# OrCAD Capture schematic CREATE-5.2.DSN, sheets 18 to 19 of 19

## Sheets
18 P16: Back access 50 pin conn: size Custom; title: Bottom Conn
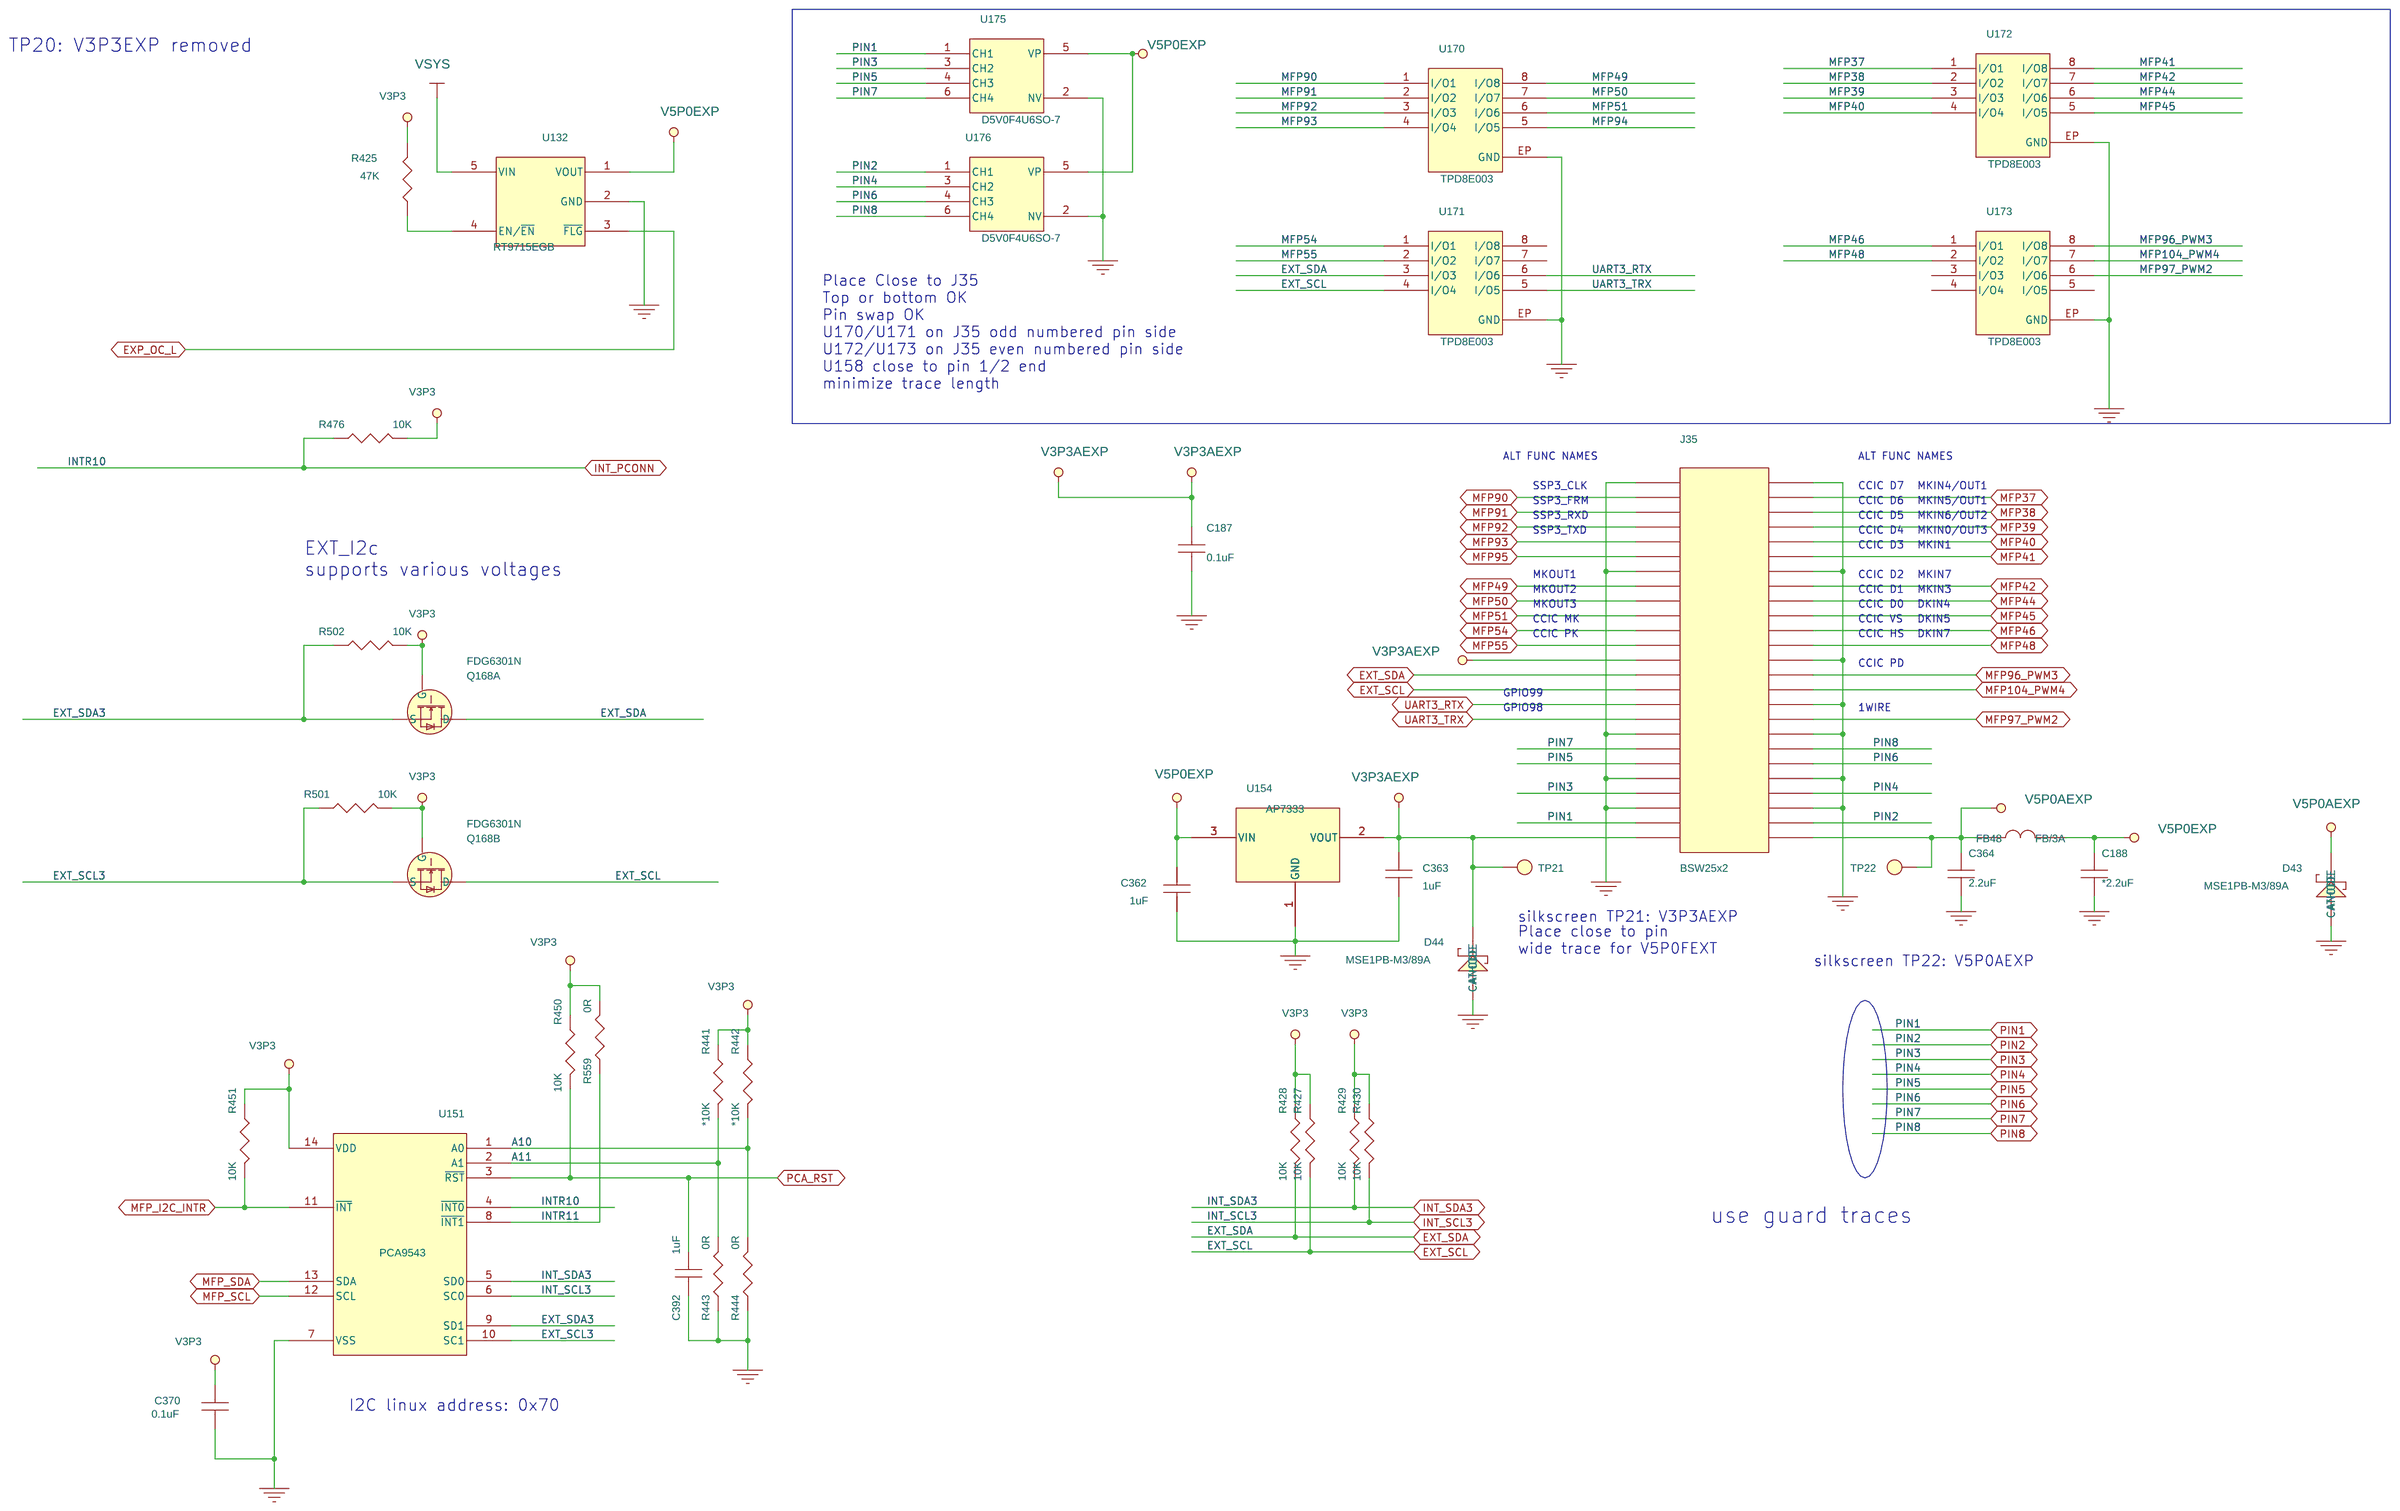
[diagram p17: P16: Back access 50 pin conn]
19 P15: Front access 8 pin conn 2: size Custom; title: Front Conn 2
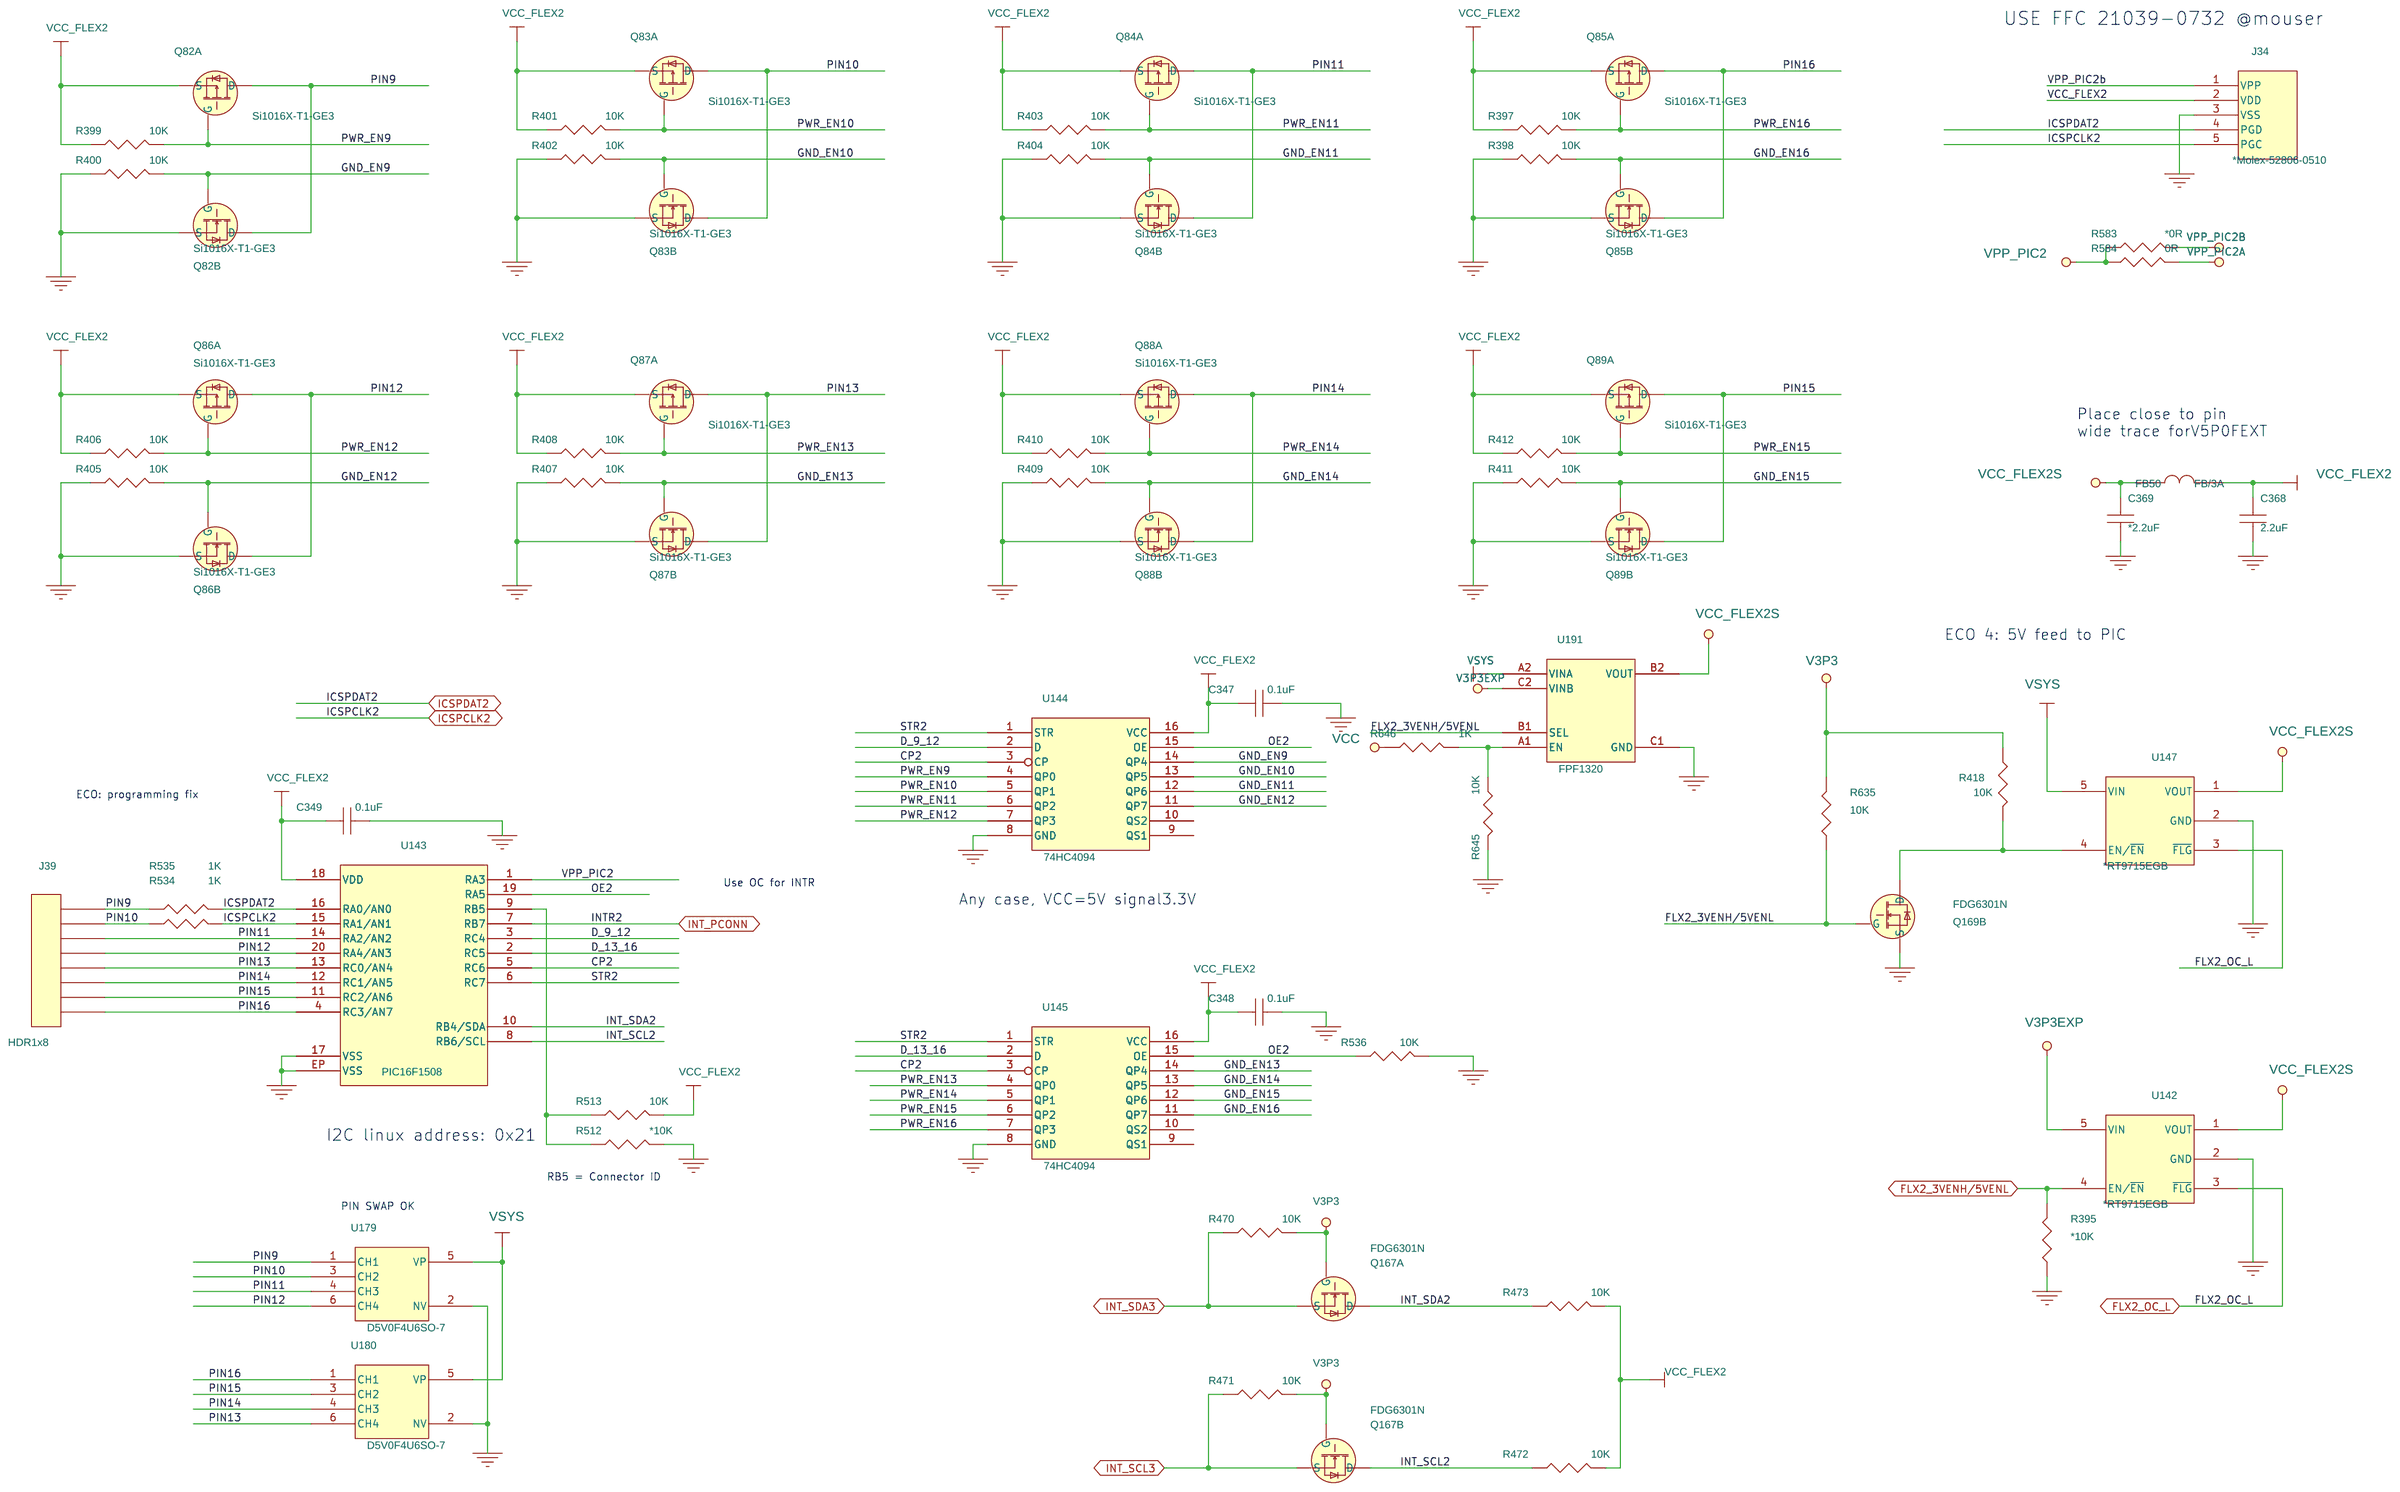
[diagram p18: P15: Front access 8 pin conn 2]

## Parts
sheet P14: Front access 8 pin conn 1
Q169  FDG6301N  [SC70-6]  (sections A,B)
sheet P15: Front access 8 pin conn 2
C347  0.1uF  [C-0402]
C348  0.1uF  [C-0402]
C349  0.1uF  [C-0402]
C368  2.2uF  [C-0402]
C369  *2.2uF  [C-0402]
FB50  FB/3A  [L-0603]
J34  *Molex-52806-0510  [Molex_52806_0510]
J39  HDR1x8  [HDR1x8_100milSMT]
Q82  Si1016X-T1-GE3  [SOT563]  (sections A,B)
Q83  Si1016X-T1-GE3  [SOT563]  (sections A,B)
Q84  Si1016X-T1-GE3  [SOT563]  (sections A,B)
Q85  Si1016X-T1-GE3  [SOT563]  (sections A,B)
Q86  Si1016X-T1-GE3  [SOT563]  (sections A,B)
Q87  Si1016X-T1-GE3  [SOT563]  (sections A,B)
Q88  Si1016X-T1-GE3  [SOT563]  (sections A,B)
Q89  Si1016X-T1-GE3  [SOT563]  (sections A,B)
Q167  FDG6301N  [SC70-6]  (sections A,B)
R395  *10K  [R-0402]
R397  10K  [R-0201]
R398  10K  [R-0201]
R399  10K  [R-0201]
R400  10K  [R-0201]
R401  10K  [R-0201]
R402  10K  [R-0201]
R403  10K  [R-0201]
R404  10K  [R-0201]
R405  10K  [R-0201]
R406  10K  [R-0201]
R407  10K  [R-0201]
R408  10K  [R-0201]
R409  10K  [R-0201]
R410  10K  [R-0201]
R411  10K  [R-0201]
R412  10K  [R-0201]
R418  10K  [R-0201]
R470  10K  [R-0201]
R471  10K  [R-0201]
R472  10K  [R-0201]
R473  10K  [R-0201]
R512  *10K  [R-0201]
R513  10K  [R-0201]
R534  1K  [R-0402]
R535  1K  [R-0402]
R536  10K  [R-0201]
R583  *0R  [R-0402]
R584  0R  [R-0402]
R635  10K  [R-0201]
R645  10K  [R-0402]
R646  1K  [R-0402]
U142  *RT9715EGB  [SOT23-5]
U143  PIC16F1508  [QFN20]
U144  74HC4094  [TSSOP16]
U145  74HC4094  [TSSOP16]
U147  *RT9715EGB  [SOT23-5]
U179  D5V0F4U6SO-7  [SC-74]
U180  D5V0F4U6SO-7  [SC-74]
U191  FPF1320  [6WLCSP]
sheet P16: Back access 50 pin conn
C187  0.1uF  [C-0402]
C188  *2.2uF  [C-0402]
C362  1uF  [C0402]
C363  1uF  [C0402]
C364  2.2uF  [C-0402]
C370  0.1uF  [C-0402]
C392  1uF  [C0402]
D43  MSE1PB-M3/89A  [MicroSMP]
D44  MSE1PB-M3/89A  [MicroSMP]
FB48  FB/3A  [L-0603]
J35  BSW25x2  [RCPT25x2_100mil_BOT]
Q168  FDG6301N  [SC70-6]  (sections A,B)
R425  47K  [R-0402]
R427  10K  [R-0402]
R428  10K  [R-0402]
R429  10K  [R-0402]
R430  10K  [R-0402]
R441  *10K  [R-0402]
R442  *10K  [R-0402]
R443  0R  [R-0402]
R444  0R  [R-0402]
R450  10K  [R-0402]
R451  10K  [R-0402]
R476  10K  [R-0402]
R501  10K  [R-0402]
R502  10K  [R-0402]
R559  0R  [R-0402]
TP21  *T_POINT  [TP040]
TP22  *T_POINT  [TP040]
U132  RT9715EGB  [SOT23-5]
U151  PCA9543  [soic14-50-157]
U154  AP7333  [SOT23R]
U170  TPD8E003  [WSON8EP]
U171  TPD8E003  [WSON8EP]
U172  TPD8E003  [WSON8EP]
U173  TPD8E003  [WSON8EP]
U175  D5V0F4U6SO-7  [SC-74]
U176  D5V0F4U6SO-7  [SC-74]

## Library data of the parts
Q169 = NMOS-DUAL6-sc70: Desc: MOSFET 2N-CH 25V 0.22A SC70-6; Vendor: Fairchild; x: MOSFET 2N-CH 25V 0.22A SC70-6
C347-C349 = CAPACITOR_NON-POL: Desc: CAP CER .10UF 10V X7R 0402; OPTION: DBG; Part Num: C1005X7R1A104K; Vendor: TDK
C188 C364 C368 C369 = CAP_NP_2: Desc: CAP CER 2.2UF 10V 10% X5R 0402; Part Num: C1005X5R1A225K; Vendor: TDK
FB48 FB50 = FERRITE_BEAD_0: Desc: FERRITE CHIP 120 OHM 3000MA 0603; Part Num: BLM18KG121TN1; Vendor: Murata
J34 = PIC_DEBUG_PAD: Desc: CONN FFC/FPC 5POS 1MM VERT T/H; Part Num: 52806-0510; Vendor: Molex
J39 = CON8: Desc: CONN HEADER FEMALE 8POS .1" GOLD; Part Num: SSM-108-F-SV; Vendor: Samtec
Q82-Q89 = CMOS-DUAL: Desc: MOSFET N/P-CH 20V 600/350 SC89-6; Vendor: Vishay
Q167 Q168 = NMOS-DUAL6-sc70: Desc: MOSFET 2N-CH 25V 0.22A SC70-6; Vendor: Fairchild
R395 R418 = R_0: Desc: RES 10K OHM 1/20W 5% 0201 SMD; Mfr: Generic; Part Num: ERJ-1GEJ103C; Vendor: Panasonic; d: RES 1K OHM 1/10W 1% 0402 SMD
R397-R412 R645 = R_0: Desc: RES 10K OHM 1/20W 5% 0201 SMD; Mfr: Generic; Part Num: ERJ-1GEJ103C; Vendor: Panasonic
R470 R471 R512 R513 R536 R635 = Res_0: Desc: RES 10K OHM 1/20W 5% 0201 SMD; Part Num: ERJ-1GEJ103C; Vendor: Panasonic
R472 R473 = Res_0: Desc: RES 10K OHM 1/20W 5% 0201 SMD; Mfr: Generic; Part Num: ERJ-1GEJ103C; Vendor: Panasonic
R534 R535 = Res_0: Desc: RES 1K OHM 1/10W 1% 0402 SMD; Mfr: Generic; Part Num: ERJ-2RKF1001X; Vendor: Panasonic
R583 = Res_0: Desc: RES 0.0 OHM 1/10W 0402 SMD; Mfr: Generic; Part Num: ERJ-2GE0R00X; Vendor: Panasonic
R584 = Res_0: Desc: RES 0.0 OHM 1/10W 0402 SMD; Mfr: Generic; Part Num: ERJ-2GE0R00X; Vendor: Panasonic; ccc: RES 0.0 OHM 1/10W 0402 SMD
R646 = Res_0: Desc: RES 1K OHM 1/10W 1% 0402 SMD; Part Num: ERJ-2RKF1001X; Vendor: Panasonic
U142 U147 = RT9517SOT23-5: Desc: IC PWR SW USB 1.1A SOT23-5; Part Num: RT9715EGB; Vendor: Richtek
U143 = PIC16F1508QFN: Vendor: microchip
U144 U145 = 74HC4094
U175 U176 U179 U180 = CM1293A: Desc: TVS DIODE 5.5VWM 12VC SOT26; Vendor: Diodes
U191 = FPF1321
C187 = CAP_NP: Desc: CAP CER .10UF 10V X7R 0402; Function Code: VGA; Part Num: C1005X7R1A104K; Part Number: CH41006K911; Vendor: TDK
C362 C363 C392 = CAP_NP_0: Desc: CAP CER 1UF 10V 10% X5R 0402; OPTION: LIPO; Part Num: C1005X5R1A105K050BB; Vendor: TDK; ccc: CAP CER 1UF 10V 10% X5R 0402
C370 = CAP_NP_1: Desc: CAP CER .10UF 10V X7R 0402; Part Num: C1005X7R1A104K; Vendor: TDK
D43 D44 = DIODE_SCHOTTKY: Desc: DIODE ESD PROT 1A 100V MICROSMP; Vendor: Vishay
J35 = CON50A: Desc: CONN RCPT 50POS .100" DBL GOLD BOTTOM ENTRY; Part Num: BSW-125-04-L-D; Vendor: Samtec
R425 = Res_0: Desc: RES 47K OHM 1/10W 1% 0402 SMD; Part Num: ERJ-2RKF4702X; Vendor: Panasonic
R427-R430 R441 R442 R450 R451 = Res_0: Desc: RES 10K OHM 1/10W 5% 0402 SMD; Mfr: Generic; Part Num: ERJ-2GEJ103X; Vendor: Panasonic
R443 R444 R559 = R_0: Desc: RES 0.0 OHM 1/10W 0402 SMD; Mfr: Generic; Part Num: ERJ-2GE0R00X; Vendor: Panasonic
R476 R501 R502 = Res_0: Desc: RES 10K OHM 1/10W 5% 0402 SMD; Part Num: ERJ-2GEJ103X; Vendor: Panasonic
TP21 TP22 = T_POINT: Desc: SMT Test Point; Part Num: NA; Vendor: Test
U132 = RT9517SOT23-5: Desc: IC PWR SW USB 1.1A SOT23-5; Vendor: Richtek
U151 = PCA9543: Desc: IC I2C SWITCH 2CH 14-SOIC; MFG: NXP; MFG_PN: PCA9543AD,118; Part Num: PCA9543AD,118; Vendor: NXP
U154 = AP7333
U170-U173 = TPD8E003

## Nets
FLX2_3VENH/5VENL: Q169.5(G) R395.1 R635.1 U142.4(EN/~{EN}) U191.B1(SEL) ; also on sheet 1
GND: C187.2 C188.2 C347.2 C348.2 C349.2 C362.2 C363.2 C364.2 C368.2 C369.2 C370.2 C392.2 D43.1(ANODE) D44.1(ANODE) J34.3(VSS) J35.1 J35.2 J35.13 J35.14 J35.26 J35.32 J35.35 J35.36 J35.41 J35.42 J35.45 J35.46 Q82.1(S) Q83.1(S) Q84.1(S) Q85.1(S) Q86.1(S) Q87.1(S) Q88.1(S) Q89.1(S) Q169.4(S) R395.2 R398.1 R400.1 R402.1 R404.1 R405.1 R407.1 R409.1 R411.1 R443.1 R444.1 R512.2 R536.1 R645.1 U132.2(GND) U142.2(GND) U143.17(VSS) U143.EP(VSS) U144.8(GND) U145.8(GND) U147.2(GND) U151.7(VSS) U154.1(GND) U170.EP(GND) U171.EP(GND) U172.EP(GND) U173.EP(GND) U175.2(NV) U176.2(NV) U179.2(NV) U180.2(NV) U191.C1(GND) ; also on sheet 1 2 3 4 5 6 7 8 10 13 14 16 17
GND_EN9: Q82.2(G) R400.2 U144.14(QP4)
GND_EN10: Q83.2(G) R402.2 U144.13(QP5)
GND_EN11: Q84.2(G) R404.2 U144.12(QP6)
GND_EN12: Q86.2(G) R405.2 U144.11(QP7)
GND_EN13: Q87.2(G) R407.2 U145.14(QP4)
GND_EN14: Q88.2(G) R409.2 U145.13(QP5)
GND_EN15: Q89.2(G) R411.2 U145.12(QP6)
GND_EN16: Q85.2(G) R398.2 U145.11(QP7)
V3P3: C370.1 Q167.2(G) Q167.5(G) Q168.2(G) Q168.5(G) R418.2 R425.1 R427.1 R428.1 R429.1 R430.1 R441.1 R442.1 R450.1 R451.1 R470.2 R471.2 R476.2 R501.2 R502.2 R559.2 R635.2 R646.1 U151.14(VDD) ; also on sheet 1 2 3 4 5 6 7 8 10 13 14 16 17
V3P3AEXP: C187.1 C363.1 D44.2(CATHODE) J35.25 J35.49 TP21.1(TP) U142.5(VIN) U154.2(VOUT) U191.C2(VINB) ; also on sheet 17
V5P0AEXP: C364.1 D43.2(CATHODE) FB48.1 J35.50 TP22.1(TP)
V5P0EXP: C188.1 C362.1 FB48.2 U132.1(VOUT) U154.3(VIN) U175.5(VP) U176.5(VP)
VCC_FLEX2: C347.1 C348.1 C349.1 C368.1 FB50.2 J34.2(VDD) Q82.4(S) Q83.4(S) Q84.4(S) Q85.4(S) Q86.4(S) Q87.4(S) Q88.4(S) Q89.4(S) R397.1 R399.1 R401.1 R403.1 R406.1 R408.1 R410.1 R412.1 R472.1 R473.1 R513.2 U143.18(VDD) U144.16(VCC) U145.16(VCC) ; also on sheet 7
VCC_FLEX2S: C369.1 FB50.1 U142.1(VOUT) U147.1(VOUT) U191.B2(VOUT)
A10: R442.2 R444.2 U151.1(A0)
A11: R441.2 R443.2 U151.2(A1)
CP2: U143.5(RC6) U144.3(CP) U145.3(CP)
D_9_12: U143.3(RC4) U144.2(D)
D_13_16: U143.2(RC5) U145.2(D)
EXP_OC_L: U132.3(~{FLG}) ; also on sheet 1
EXT_SCL: J35.29 Q168.3(D) R427.2 U171.4(I/O4)
EXT_SCL3: Q168.4(S) R501.1 U151.10(SC1)
EXT_SDA: J35.27 Q168.6(D) R428.2 U171.3(I/O3)
EXT_SDA3: Q168.1(S) R502.1 U151.9(SD1)
FLX2_OC_L: U142.3(~{FLG}) U147.3(~{FLG}) ; also on sheet 1
ICSPCLK2: J34.5(PGC) R534.2 U143.15(RA1/AN1) ; also on sheet 7
ICSPDAT2: J34.4(PGD) R535.2 U143.16(RA0/AN0) ; also on sheet 7
INT_PCONN: R476.1 U143.7(RB7) U151.4(~{INT0}) ; also on sheet 17
INT_SCL2: Q167.3(D) R472.2 U143.8(RB6/SCL)
INT_SCL3: Q167.4(S) R430.2 R471.1 U151.6(SC0) ; also on sheet 17
INT_SDA2: Q167.6(D) R473.2 U143.10(RB4/SDA)
INT_SDA3: Q167.1(S) R429.2 R470.1 U151.5(SD0) ; also on sheet 17
INTR11: R559.1 U151.8(~{INT1})
MFP37: J35.4 U172.1(I/O1) ; also on sheet 14
MFP38: J35.6 U172.2(I/O2) ; also on sheet 14
MFP39: J35.8 U172.3(I/O3) ; also on sheet 14
MFP40: J35.10 U172.4(I/O4) ; also on sheet 14
MFP41: J35.12 U172.8(I/O8) ; also on sheet 14
MFP42: J35.16 U172.7(I/O7) ; also on sheet 14
MFP44: J35.18 U172.6(I/O6) ; also on sheet 14
MFP45: J35.20 U172.5(I/O5) ; also on sheet 14
MFP46: J35.22 U173.1(I/O1) ; also on sheet 14
MFP48: J35.24 U173.2(I/O2) ; also on sheet 14
MFP49: J35.15 U170.8(I/O8) ; also on sheet 14
MFP50: J35.17 U170.7(I/O7) ; also on sheet 14
MFP51: J35.19 U170.6(I/O6) ; also on sheet 14
MFP54: J35.21 U171.1(I/O1) ; also on sheet 14
MFP55: J35.23 U171.2(I/O2) ; also on sheet 14
MFP90: J35.3 U170.1(I/O1) ; also on sheet 6 14
MFP91: J35.5 U170.2(I/O2) ; also on sheet 6 14
MFP92: J35.7 U170.3(I/O3) ; also on sheet 6 14
MFP93: J35.9 U170.4(I/O4) ; also on sheet 6 14
MFP94: U170.5(I/O5)
MFP95: J35.11 ; also on sheet 14
MFP96_PWM3: J35.28 U173.8(I/O8) ; also on sheet 14
MFP97_PWM2: J35.34 U173.6(I/O6) ; also on sheet 14
MFP104_PWM4: J35.30 U173.7(I/O7) ; also on sheet 14
MFP_I2C_INTR: R451.2 U151.11(~{INT}) ; also on sheet 1
MFP_SCL: U151.12(SCL) ; also on sheet 4 6 14 16
MFP_SDA: U151.13(SDA) ; also on sheet 4 6 14 16
OE2: R536.2 U143.19(RA5) U144.15(OE) U145.15(OE)
PCA_RST: C392.1 R450.2 U151.3(~{RST}) ; also on sheet 14
PIN1: J35.47 U175.1(CH1) ; also on sheet 17
PIN2: J35.48 U176.1(CH1) ; also on sheet 17
PIN3: J35.43 U175.3(CH2) ; also on sheet 17
PIN4: J35.44 U176.3(CH2) ; also on sheet 17
PIN5: J35.39 U175.4(CH3) ; also on sheet 17
PIN6: J35.40 U176.4(CH3) ; also on sheet 17
PIN7: J35.37 U175.6(CH4) ; also on sheet 17
PIN8: J35.38 U176.6(CH4) ; also on sheet 17
PIN9: J39.1 Q82.3(D) Q82.6(D) R535.1 U179.1(CH1)
PIN10: J39.2 Q83.3(D) Q83.6(D) R534.1 U179.3(CH2)
PIN11: J39.3 Q84.3(D) Q84.6(D) U143.14(RA2/AN2) U179.4(CH3)
PIN12: J39.4 Q86.3(D) Q86.6(D) U143.20(RA4/AN3) U179.6(CH4)
PIN13: J39.5 Q87.3(D) Q87.6(D) U143.13(RC0/AN4) U180.6(CH4)
PIN14: J39.6 Q88.3(D) Q88.6(D) U143.12(RC1/AN5) U180.4(CH3)
PIN15: J39.7 Q89.3(D) Q89.6(D) U143.11(RC2/AN6) U180.3(CH2)
PIN16: J39.8 Q85.3(D) Q85.6(D) U143.4(RC3/AN7) U180.1(CH1)
PWR_EN9: Q82.5(G) R399.2 U144.4(QP0)
PWR_EN10: Q83.5(G) R401.2 U144.5(QP1)
PWR_EN11: Q84.5(G) R403.2 U144.6(QP2)
PWR_EN12: Q86.5(G) R406.2 U144.7(QP3)
PWR_EN13: Q87.5(G) R408.2 U145.4(QP0)
PWR_EN14: Q88.5(G) R410.2 U145.5(QP1)
PWR_EN15: Q89.5(G) R412.2 U145.6(QP2)
PWR_EN16: Q85.5(G) R397.2 U145.7(QP3)
STR2: U143.6(RC7) U144.1(STR) U145.1(STR)
UART3_RTX: J35.31 U171.6(I/O6) ; also on sheet 14
UART3_TRX: J35.33 U171.5(I/O5) ; also on sheet 14
VPP_PIC2: R583.1 R584.1 U143.1(RA3)
VPP_PIC2a: R584.2 ; also on sheet 7
VPP_PIC2b: J34.1(VPP) R583.2
VSYS: U132.5(VIN) U147.5(VIN) U179.5(VP) U180.5(VP) U191.A2(VINA) ; also on sheet 2 3 6 10 13 17
N42788794: R425.2 U132.4(EN/~{EN})
N42943757: Q169.3(D) R418.1 U147.4(EN/~{EN})
N43247441: R512.1 R513.1 U143.9(RB5)
N44348152: R645.2 R646.2 U191.A1(EN)

Not connected (* = marked no-connect by the designer): U144 9(QS1) 10(QS2); U145 9(QS1) 10(QS2); U171 7(I/O7) 8(I/O8); U173 3(I/O3) 4(I/O4) 5(I/O5)

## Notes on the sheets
sheet 18
- TP20: V3P3EXP removed
- Place Close to J35
  Top or bottom OK
  Pin swap OK
  U170/U171 on J35 odd numbered pin side
  U172/U173 on J35 even numbered pin side
  U158 close to pin 1/2 end
  minimize trace length
- ALT FUNC NAMES
- ALT FUNC NAMES
- SSP3_CLK
- CCIC D7
- MKIN4/OUT1
- SSP3_FRM
- CCIC D6
- MKIN5/OUT1
- SSP3_RXD
- CCIC D5
- MKIN6/OUT2
- SSP3_TXD
- CCIC D4
- MKIN0/OUT3
- EXT_I2c
  supports various voltages
- CCIC D3
- MKIN1
- MKOUT1
- CCIC D2
- MKIN7
- MKOUT2
- CCIC D1
- MKIN3
- MKOUT3
- CCIC D0
- DKIN4
- CCIC MK
- CCIC VS
- DKIN5
- CCIC PK
- CCIC HS
- DKIN7
- CCIC PD
- GPIO99
- GPIO98
- 1WIRE
- silkscreen TP21: V3P3AEXP
- Place close to pin
  wide trace for V5P0FEXT
- silkscreen TP22: V5P0AEXP
- use guard traces
- I2C linux address: 0x70
sheet 19
- USE FFC 21039-0732 @mouser
- Place close to pin
  wide trace forV5P0FEXT
- ECO 4: 5V feed to PIC
- ECO: programming fix
- Use OC for INTR
- Any case, VCC=5V signal3.3V
- I2C linux address: 0x21
- RB5 = Connector ID
- PIN SWAP OK
